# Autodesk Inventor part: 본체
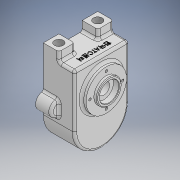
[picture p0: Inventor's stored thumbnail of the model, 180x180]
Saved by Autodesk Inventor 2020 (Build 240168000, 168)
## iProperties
Created: 2024-03
Part Number: 본체
Material: 일반
Document SubType Name: Modeling
Designer: 1강의실14
Density: 1 g/cm^3
Appearance: 기본값
Author: 1강의실14
## Parameters: d0 = 103 mm, d3 = 0, d4 = 35 mm, d5 = 35 mm, d6 = 52 mm, d7 = 6 mm, d8 = 0, d9 = 32 mm, d10 = 4 mm, d11 = 0, d12 = 25 mm, d13 = 7.3 mm, d14 = 0, d15 = 35 mm, d16 = 36 mm, d17 = 33 mm, d18 = 36 mm, d19 = 28 mm, d22 = 0, d26 = 0, d27 = 15 mm, d29 = 0, d30 = 7 mm, d31 = 60 deg, d32 = 90 deg, d33 = 42 mm, d34 = 3.242 mm, d35 = 8 mm, d36 = 4 mm, d37 = 2 mm, d38 = 90 deg, d40 = 118 deg, d42 = 360 deg, d44 = 3.5 mm, d45 = 0.7 mm, d46 = 30 deg, d47 = 90 deg, d48 = 51.5 mm, d51 = 0, d52 = 9 mm, d53 = 85 mm, d54 = 4.134 mm, d56 = 4 mm, d57 = 2 mm, d58 = 90 deg, d59 = 12 mm, d60 = 118 deg, d89 = 1 mm, d90 = 2 mm, d91 = 45 deg, d92 = 3 mm, d109 = 51.5 mm, d110 = 25 mm, d111 = 51.5 mm, d112 = 8 mm, d114 = 51.5 mm, d115 = 6 mm, d116 = 0, d117 = 0, d122 = 12 mm, d123 = 0, d128 = 10.5 mm, d129 = 11 mm, d130 = 0.62479 mm, d131 = 10.589 mm, d132 = 4 mm, d133 = 2 mm, d134 = 90 deg, d135 = 16 mm, d136 = 118 deg, d137 = 3 mm, d139 = 0.5 mm, d140 = 0
